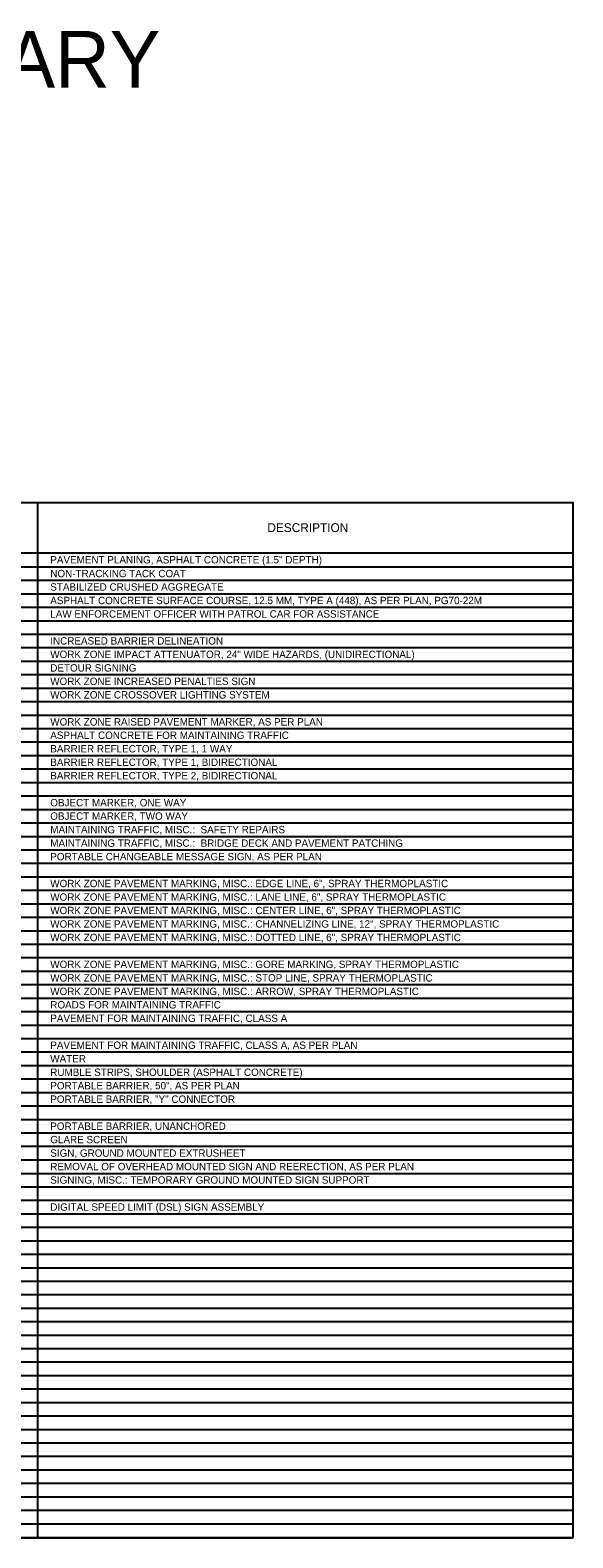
# Model space of a CAD drawing. Extents: x 91011267 to 91012802, y 37012737 to 37014266.
# Drawn here: x 91012252 to 91012802, y 37012737 to 37014266 of the extents above; entities that cross this region are included whole.
import ezdxf

# ---------------------------------------------------------------- set-up
doc = ezdxf.new("R2010")
doc.units = 0
doc.layers.add('SC_Scratch2', color=7, linetype='Continuous')
doc.layers.add('SH_Data', color=7, linetype='Continuous')

msp = doc.modelspace()

# ---------------------------------------------------------------- linework, layer by layer
at = {"layer": 'SC_Scratch2'}
msp.add_lwpolyline([(91011277.4, 37013787.1), (91012802.4, 37013787.1), (91012802.4, 37012737.1), (91011277.4, 37012737.1)], close=True, dxfattribs=at)
at = {"layer": 'SH_Data'}
for p, q in [((91012030, 37013787.1), (91012802.4, 37013787.1)), ((91012259.4, 37013787.1), (91012259.4, 37013708.3)), ((91012802.4, 37013787.1), (91012802.4, 37013708.3)), ((91012030, 37013736.3), (91012802.4, 37013736.3)), ((91012030, 37013722), (91012802.4, 37013722)), ((91012030, 37013708.3), (91012802.4, 37013708.3)), ((91012259.4, 37013708.3), (91012259.4, 37013694.7)), ((91012802.4, 37013708.3), (91012802.4, 37013694.7)), ((91012030, 37013694.7), (91012802.4, 37013694.7)), ((91012259.4, 37013694.7), (91012259.4, 37013626.3)), ((91012802.4, 37013694.7), (91012802.4, 37013626.3)), ((91012030, 37013681), (91012802.4, 37013681)), ((91012030, 37013667.3), (91012802.4, 37013667.3)), ((91012030, 37013653.6), (91012802.4, 37013653.6)), ((91012030, 37013640), (91012802.4, 37013640)), ((91012030, 37013626.3), (91012802.4, 37013626.3)), ((91012259.4, 37013626.3), (91012259.4, 37013612.6)), ((91012802.4, 37013626.3), (91012802.4, 37013612.6)), ((91012030, 37013612.6), (91012802.4, 37013612.6)), ((91012259.4, 37013612.6), (91012259.4, 37013599)), ((91012802.4, 37013612.6), (91012802.4, 37013599)), ((91012030, 37013599), (91012802.4, 37013599)), ((91012259.4, 37013599), (91012259.4, 37013503.3)), ((91012802.4, 37013599), (91012802.4, 37013503.3)), ((91012030, 37013585.3), (91012802.4, 37013585.3)), ((91012030, 37013571.6), (91012802.4, 37013571.6)), ((91012030, 37013558), (91012802.4, 37013558)), ((91012030, 37013544.3), (91012802.4, 37013544.3)), ((91012030, 37013530.6), (91012802.4, 37013530.6)), ((91012030, 37013516.9), (91012802.4, 37013516.9)), ((91012030, 37013503.3), (91012802.4, 37013503.3)), ((91012259.4, 37013503.3), (91012259.4, 37013489.6)), ((91012802.4, 37013503.3), (91012802.4, 37013489.6)), ((91012030, 37013489.6), (91012802.4, 37013489.6)), ((91012259.4, 37013489.6), (91012259.4, 37013462.3)), ((91012802.4, 37013489.6), (91012802.4, 37013462.3)), ((91012030, 37013475.9), (91012802.4, 37013475.9)), ((91012030, 37013462.3), (91012802.4, 37013462.3)), ((91012259.4, 37013462.3), (91012259.4, 37013448.6)), ((91012802.4, 37013462.3), (91012802.4, 37013448.6)), ((91012030, 37013448.6), (91012802.4, 37013448.6)), ((91012259.4, 37013448.6), (91012259.4, 37013434.9)), ((91012802.4, 37013448.6), (91012802.4, 37013434.9)), ((91012030, 37013434.9), (91012802.4, 37013434.9)), ((91012259.4, 37013434.9), (91012259.4, 37013421.3)), ((91012802.4, 37013434.9), (91012802.4, 37013421.3)), ((91012030, 37013421.3), (91012802.4, 37013421.3)), ((91012259.4, 37013421.3), (91012259.4, 37013216.2)), ((91012802.4, 37013421.3), (91012802.4, 37013216.2)), ((91012030, 37013407.6), (91012802.4, 37013407.6)), ((91012030, 37013393.9), (91012802.4, 37013393.9)), ((91012030, 37013380.2), (91012802.4, 37013380.2)), ((91012030, 37013366.6), (91012802.4, 37013366.6)), ((91012030, 37013352.9), (91012802.4, 37013352.9)), ((91012030, 37013339.2), (91012802.4, 37013339.2)), ((91012030, 37013325.6), (91012802.4, 37013325.6)), ((91012030, 37013311.9), (91012802.4, 37013311.9)), ((91012030, 37013298.2), (91012802.4, 37013298.2)), ((91012030, 37013284.6), (91012802.4, 37013284.6)), ((91012030, 37013270.9), (91012802.4, 37013270.9)), ((91012030, 37013257.2), (91012802.4, 37013257.2)), ((91012030, 37013243.5), (91012802.4, 37013243.5)), ((91012030, 37013229.9), (91012802.4, 37013229.9)), ((91012030, 37013216.2), (91012802.4, 37013216.2)), ((91012259.4, 37013216.2), (91012259.4, 37013202.5)), ((91012802.4, 37013216.2), (91012802.4, 37013202.5)), ((91012030, 37013202.5), (91012802.4, 37013202.5)), ((91012259.4, 37013202.5), (91012259.4, 37013188.9)), ((91012802.4, 37013202.5), (91012802.4, 37013188.9)), ((91012030, 37013188.9), (91012802.4, 37013188.9)), ((91012259.4, 37013188.9), (91012259.4, 37013147.9)), ((91012802.4, 37013188.9), (91012802.4, 37013147.9)), ((91012030, 37013175.2), (91012802.4, 37013175.2)), ((91012030, 37013161.5), (91012802.4, 37013161.5)), ((91012030, 37013147.9), (91012802.4, 37013147.9)), ((91012030, 37013134.2), (91012802.4, 37013134.2)), ((91012259.4, 37013147.9), (91012259.4, 37013134.2)), ((91012259.4, 37013134.2), (91012259.4, 37013120.5)), ((91012802.4, 37013147.9), (91012802.4, 37013134.2)), ((91012802.4, 37013134.2), (91012802.4, 37013120.5)), ((91012030, 37013120.5), (91012802.4, 37013120.5)), ((91012259.4, 37013120.5), (91012259.4, 37013079.5)), ((91012802.4, 37013120.5), (91012802.4, 37013079.5)), ((91012030, 37013106.8), (91012802.4, 37013106.8)), ((91012030, 37013093.2), (91012802.4, 37013093.2)), ((91012030, 37013079.5), (91012802.4, 37013079.5)), ((91012259.4, 37013079.5), (91012259.4, 37013065.8)), ((91012802.4, 37013079.5), (91012802.4, 37013065.8)), ((91012030, 37013065.8), (91012802.4, 37013065.8)), ((91012259.4, 37013065.8), (91012259.4, 37013052.2)), ((91012802.4, 37013065.8), (91012802.4, 37013052.2)), ((91012030, 37013052.2), (91012802.4, 37013052.2)), ((91012259.4, 37013052.2), (91012259.4, 37012737.1)), ((91012802.4, 37013052.2), (91012802.4, 37012737.1)), ((91012030, 37013038.5), (91012802.4, 37013038.5)), ((91012030, 37013024.8), (91012802.4, 37013024.8)), ((91012030, 37013011.1), (91012802.4, 37013011.1)), ((91012030, 37012997.5), (91012802.4, 37012997.5)), ((91012030, 37012983.8), (91012802.4, 37012983.8)), ((91012030, 37012970.1), (91012802.4, 37012970.1)), ((91012030, 37012956.5), (91012802.4, 37012956.5)), ((91012030, 37012942.8), (91012802.4, 37012942.8)), ((91012030, 37012929.1), (91012802.4, 37012929.1)), ((91012030, 37012915.5), (91012802.4, 37012915.5)), ((91012030, 37012901.8), (91012802.4, 37012901.8)), ((91012030, 37012888.1), (91012802.4, 37012888.1)), ((91012030, 37012874.4), (91012802.4, 37012874.4)), ((91012030, 37012860.8), (91012802.4, 37012860.8)), ((91012030, 37012847.1), (91012802.4, 37012847.1)), ((91012030, 37012833.4), (91012802.4, 37012833.4)), ((91012030, 37012819.8), (91012802.4, 37012819.8)), ((91012030, 37012806.1), (91012802.4, 37012806.1)), ((91012030, 37012792.4), (91012802.4, 37012792.4)), ((91012030, 37012778.8), (91012802.4, 37012778.8)), ((91012030, 37012765.1), (91012802.4, 37012765.1)), ((91012030, 37012751.4), (91012802.4, 37012751.4)), ((91012030, 37012737.1), (91012802.4, 37012737.1))]:
    msp.add_line(p, q, dxfattribs=at)

# ---------------------------------------------------------------- texts
at = {"layer": 'SC_Scratch2'}
msp.add_text('MOT SUBSUMMARY', height=57.415, rotation=360, dxfattribs=at).set_placement((91011641.9, 37014208))
at = {"layer": 'SH_Data'}
for s, height, p in [('DESCRIPTION', 8.983, (91012492.6, 37013757.2)), ('PAVEMENT PLANING, ASPHALT CONCRETE (1.5" DEPTH)', 7.486, (91012272.5, 37013725.4)), ('NON-TRACKING TACK COAT', 7.486, (91012272.5, 37013711.4)), ('STABILIZED CRUSHED AGGREGATE', 7.486, (91012272.5, 37013697.8)), ('ASPHALT CONCRETE SURFACE COURSE, 12.5 MM, TYPE A (448), AS PER PLAN, PG70-22M', 7.486, (91012272.5, 37013684.1)), ('LAW ENFORCEMENT OFFICER WITH PATROL CAR FOR ASSISTANCE', 7.486, (91012272.5, 37013670.4)), ('INCREASED BARRIER DELINEATION', 7.486, (91012272.5, 37013643.1)), ('WORK ZONE IMPACT ATTENUATOR, 24" WIDE HAZARDS, (UNIDIRECTIONAL)', 7.486, (91012272.5, 37013629.4)), ('DETOUR SIGNING', 7.486, (91012272.5, 37013615.7)), ('WORK ZONE INCREASED PENALTIES SIGN', 7.486, (91012272.5, 37013602.1)), ('WORK ZONE CROSSOVER LIGHTING SYSTEM', 7.486, (91012272.5, 37013588.4)), ('WORK ZONE RAISED PAVEMENT MARKER, AS PER PLAN', 7.486, (91012272.5, 37013561)), ('ASPHALT CONCRETE FOR MAINTAINING TRAFFIC', 7.486, (91012272.5, 37013547.4)), ('BARRIER REFLECTOR, TYPE 1, 1 WAY', 7.486, (91012272.5, 37013533.7)), ('BARRIER REFLECTOR, TYPE 1, BIDIRECTIONAL', 7.486, (91012272.5, 37013520)), ('BARRIER REFLECTOR, TYPE 2, BIDIRECTIONAL', 7.486, (91012272.5, 37013506.4)), ('OBJECT MARKER, ONE WAY', 7.486, (91012272.5, 37013479)), ('OBJECT MARKER, TWO WAY', 7.486, (91012272.5, 37013465.4)), ('MAINTAINING TRAFFIC, MISC.:  SAFETY REPAIRS', 7.486, (91012272.5, 37013451.7)), ('MAINTAINING TRAFFIC, MISC.:  BRIDGE DECK AND PAVEMENT PATCHING', 7.486, (91012272.5, 37013438)), ('PORTABLE CHANGEABLE MESSAGE SIGN, AS PER PLAN', 7.486, (91012272.5, 37013424.3)), ('WORK ZONE PAVEMENT MARKING, MISC.: EDGE LINE, 6", SPRAY THERMOPLASTIC', 7.486, (91012272.5, 37013397)), ('WORK ZONE PAVEMENT MARKING, MISC.: LANE LINE, 6", SPRAY THERMOPLASTIC', 7.486, (91012272.5, 37013383.3)), ('WORK ZONE PAVEMENT MARKING, MISC.: CENTER LINE, 6", SPRAY THERMOPLASTIC', 7.486, (91012272.5, 37013369.7)), ('WORK ZONE PAVEMENT MARKING, MISC.: CHANNELIZING LINE, 12", SPRAY THERMOPLASTIC', 7.486, (91012272.5, 37013356)), ('WORK ZONE PAVEMENT MARKING, MISC.: DOTTED LINE, 6", SPRAY THERMOPLASTIC', 7.486, (91012272.5, 37013342.3)), ('WORK ZONE PAVEMENT MARKING, MISC.: GORE MARKING, SPRAY THERMOPLASTIC', 7.486, (91012272.5, 37013315)), ('WORK ZONE PAVEMENT MARKING, MISC.: STOP LINE, SPRAY THERMOPLASTIC', 7.486, (91012272.5, 37013301.3)), ('WORK ZONE PAVEMENT MARKING, MISC.: ARROW, SPRAY THERMOPLASTIC', 7.486, (91012272.5, 37013287.6)), ('ROADS FOR MAINTAINING TRAFFIC', 7.486, (91012272.5, 37013274)), ('PAVEMENT FOR MAINTAINING TRAFFIC, CLASS A', 7.486, (91012272.5, 37013260.3)), ('PAVEMENT FOR MAINTAINING TRAFFIC, CLASS A, AS PER PLAN', 7.486, (91012272.5, 37013233)), ('WATER', 7.49, (91012272.5, 37013219.3)), ('RUMBLE STRIPS, SHOULDER (ASPHALT CONCRETE)', 7.486, (91012272.5, 37013205.6)), ('PORTABLE BARRIER, 50", AS PER PLAN', 7.486, (91012272.5, 37013192)), ('PORTABLE BARRIER, "Y" CONNECTOR', 7.486, (91012272.5, 37013178.3)), ('PORTABLE BARRIER, UNANCHORED', 7.486, (91012272.5, 37013150.9)), ('GLARE SCREEN', 7.486, (91012272.5, 37013137.3)), ('SIGN, GROUND MOUNTED EXTRUSHEET', 7.486, (91012272.5, 37013123.6)), ('SIGNING, MISC.: TEMPORARY GROUND MOUNTED SIGN SUPPORT', 7.486, (91012272.5, 37013096.3)), ('REMOVAL OF OVERHEAD MOUNTED SIGN AND REERECTION, AS PER PLAN', 7.486, (91012272.5, 37013109.9)), ('DIGITAL SPEED LIMIT (DSL) SIGN ASSEMBLY', 7.486, (91012272.5, 37013068.9))]:
    msp.add_text(s, height=height, dxfattribs=at).set_placement(p)

doc.saveas('drawing.dxf')
